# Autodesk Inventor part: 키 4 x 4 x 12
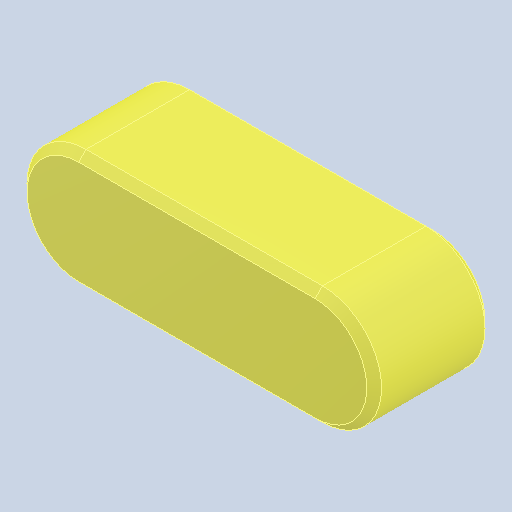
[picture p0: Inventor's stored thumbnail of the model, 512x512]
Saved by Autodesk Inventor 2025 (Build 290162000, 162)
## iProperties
Created: 2024-07
Part Number: 키 4 x 4 x 12
Material: 강철, 연강
Description: 키 및 해당 키홈
Document SubType Name: Modeling
Designer: deana
Density: 7.85 g/cm^3
Appearance: 기본값
Author: jhkim
Sending System: Autodesk Inventor 2025
Preprocessor: ST-DEVELOPER v20
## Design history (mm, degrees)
feature "Solid1"
node "솔리드1"
